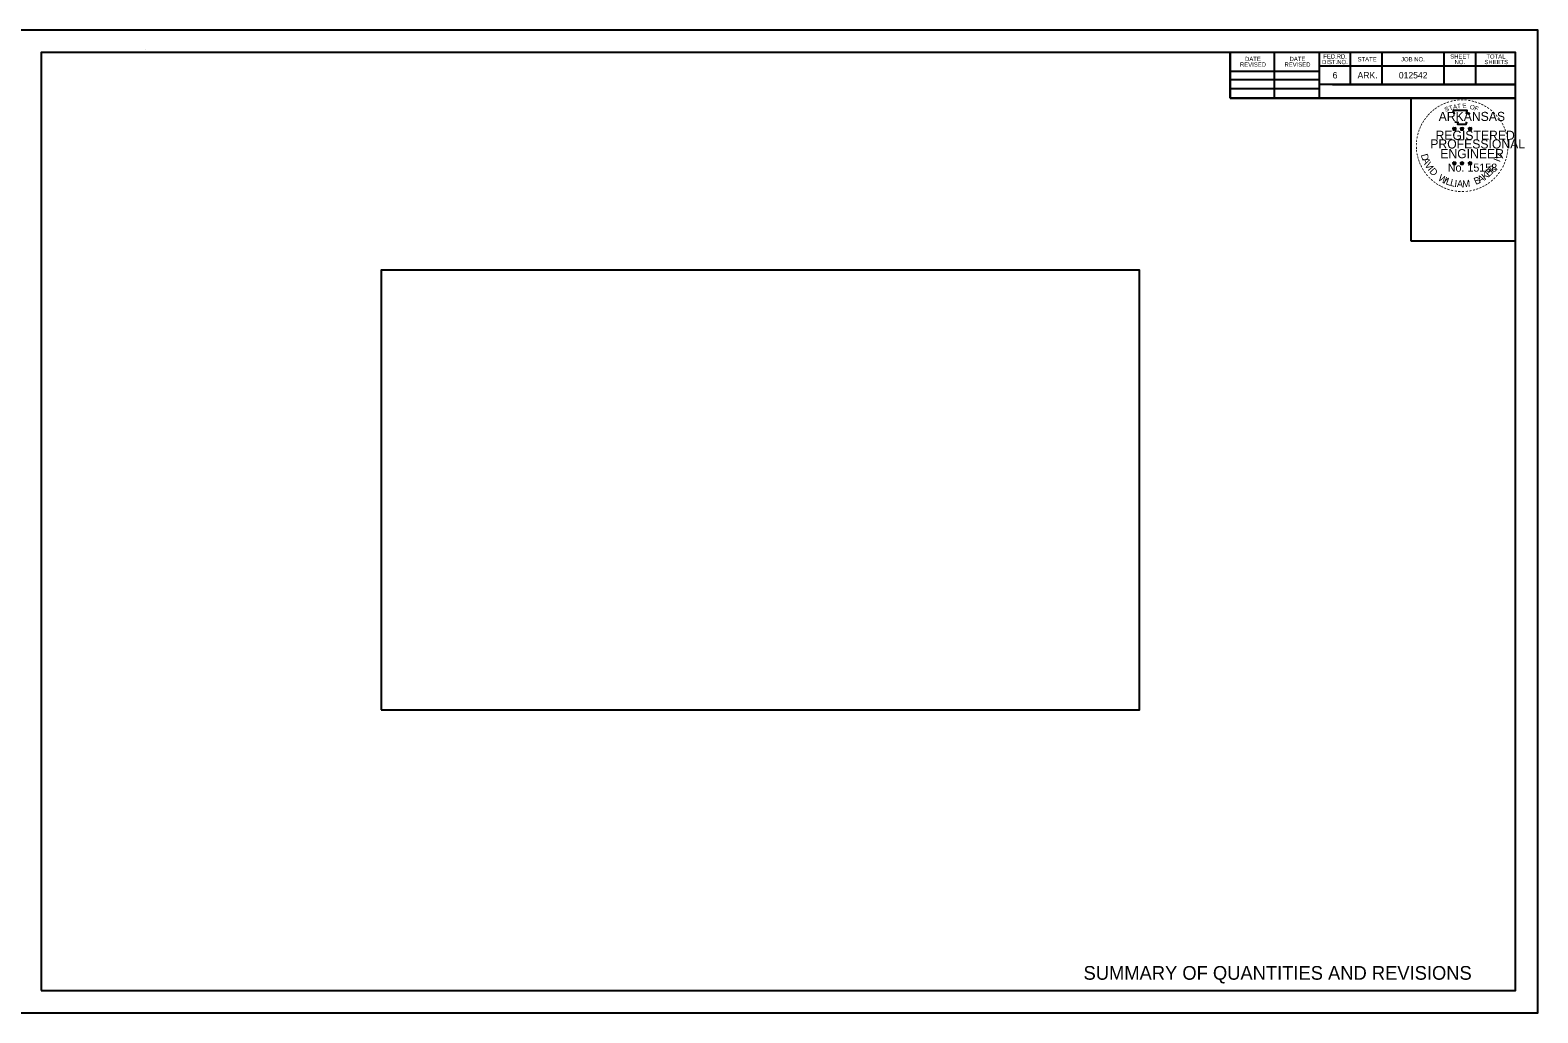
# Model space of a CAD drawing. Extents: x 2260866 to 2265966, y -3124874 to -3123774.
# Drawn here: x 2264278 to 2265966, y -3124874 to -3123774 of the extents above; entities that cross this region are included whole.
import ezdxf

# ---------------------------------------------------------------- set-up
doc = ezdxf.new("R2010")
doc.units = 0
for name, color, linetype in [('Default', 7, 'Continuous'), ('R_Border PE', 7, 'Continuous'), ('SHET_Annotations', 7, 'Continuous'), ('SHET_Border-Lines', 7, 'Continuous'), ('SHET_Border-Text', 7, 'Continuous'), ('SHET_Stamp-PE-Chief-Eng', 7, 'Continuous'), ('SHET_Stamp-Prelim', 7, 'Continuous'), ('SHET_Stamp-Seal', 7, 'Continuous')]:
    doc.layers.add(name, color=color, linetype=linetype)

msp = doc.modelspace()

# ---------------------------------------------------------------- linework, layer by layer
at = {"layer": 'Default'}
for points in [[(2264265.7, -3123773.5), (2264265.7, -3124873.5), (2265965.7, -3124873.5), (2265965.7, -3123773.5)], [(2264671.2, -3124534.4), (2265520, -3124534.4), (2265520, -3124042.2), (2264671.2, -3124042.2)]]:
    msp.add_lwpolyline(points, close=True, dxfattribs=at)
at = {"layer": 'R_Border PE'}
for p, q in [((2265872.3, -3123882), (2265872.1, -3123883.3)), ((2265872.3, -3123883.8), (2265872.3, -3123882)), ((2265872.3, -3123882), (2265872.5, -3123883.3)), ((2265880.8, -3123882), (2265880.6, -3123883.3)), ((2265880.8, -3123883.8), (2265880.8, -3123882)), ((2265880.8, -3123882), (2265881, -3123883.3)), ((2265889.8, -3123882), (2265889.6, -3123883.3)), ((2265889.8, -3123883.9), (2265889.8, -3123882)), ((2265889.8, -3123882), (2265890, -3123883.3)), ((2265870.5, -3123883.3), (2265872.3, -3123883.8)), ((2265870.5, -3123883.3), (2265871.8, -3123883.5)), ((2265870.5, -3123883.3), (2265871.7, -3123883.9)), ((2265871.2, -3123885.4), (2265872.3, -3123883.8)), ((2265871.2, -3123885.4), (2265871.8, -3123884.1)), ((2265871.2, -3123885.4), (2265872.3, -3123884.3)), ((2265874, -3123883.3), (2265872.3, -3123883.8)), ((2265873.4, -3123885.4), (2265872.3, -3123883.8)), ((2265873.4, -3123885.4), (2265872.3, -3123884.3)), ((2265874, -3123883.3), (2265872.6, -3123883.5)), ((2265873.4, -3123885.4), (2265872.7, -3123883.9)), ((2265874, -3123883.3), (2265873, -3123883.8)), ((2265879, -3123883.3), (2265880.8, -3123883.8)), ((2265879, -3123883.3), (2265880.3, -3123883.5)), ((2265879, -3123883.3), (2265880.2, -3123883.9)), ((2265879.7, -3123885.4), (2265880.8, -3123883.8)), ((2265879.7, -3123885.4), (2265880.3, -3123884.1)), ((2265879.7, -3123885.4), (2265880.8, -3123884.3)), ((2265882.6, -3123883.3), (2265880.8, -3123883.8)), ((2265881.9, -3123885.4), (2265880.8, -3123883.8)), ((2265881.9, -3123885.4), (2265880.8, -3123884.3)), ((2265882.6, -3123883.3), (2265881.1, -3123883.5)), ((2265881.9, -3123885.4), (2265881.2, -3123883.9)), ((2265882.6, -3123883.3), (2265881.5, -3123883.8)), ((2265888, -3123883.3), (2265889.8, -3123883.9)), ((2265888, -3123883.3), (2265889.3, -3123883.6)), ((2265888, -3123883.3), (2265889.2, -3123884)), ((2265888.7, -3123885.4), (2265889.8, -3123883.9)), ((2265888.7, -3123885.4), (2265889.3, -3123884.2)), ((2265888.7, -3123885.4), (2265889.8, -3123884.3)), ((2265891.6, -3123883.3), (2265889.8, -3123883.9)), ((2265890.9, -3123885.4), (2265889.8, -3123883.9)), ((2265890.9, -3123885.4), (2265889.8, -3123884.3)), ((2265891.6, -3123883.3), (2265890.1, -3123883.6)), ((2265890.9, -3123885.4), (2265890.2, -3123883.9)), ((2265891.6, -3123883.3), (2265890.5, -3123883.9)), ((2265870.5, -3123921.9), (2265872.3, -3123922.5)), ((2265870.5, -3123921.9), (2265871.8, -3123922.1)), ((2265870.5, -3123921.9), (2265871.7, -3123922.5)), ((2265871.2, -3123924), (2265872.3, -3123922.5)), ((2265871.2, -3123924), (2265871.8, -3123922.7)), ((2265871.2, -3123924), (2265872.2, -3123922.9)), ((2265872.3, -3123920.6), (2265872, -3123921.9)), ((2265873.3, -3123924), (2265872.2, -3123922.9)), ((2265872.3, -3123922.5), (2265872.3, -3123920.6)), ((2265872.3, -3123920.6), (2265872.5, -3123921.9)), ((2265874, -3123921.9), (2265872.3, -3123922.5)), ((2265873.3, -3123924), (2265872.3, -3123922.5)), ((2265874, -3123921.9), (2265872.6, -3123922.2)), ((2265873.3, -3123924), (2265872.6, -3123922.5)), ((2265874, -3123921.9), (2265873, -3123922.4)), ((2265879, -3123921.9), (2265880.8, -3123922.5)), ((2265879, -3123921.9), (2265880.3, -3123922.1)), ((2265879, -3123921.9), (2265880.2, -3123922.5)), ((2265879.7, -3123924), (2265880.8, -3123922.5)), ((2265879.7, -3123924), (2265880.3, -3123922.7)), ((2265879.7, -3123924), (2265880.8, -3123922.9)), ((2265880.8, -3123920.6), (2265880.6, -3123921.9)), ((2265880.8, -3123922.5), (2265880.8, -3123920.6)), ((2265880.8, -3123920.6), (2265881, -3123921.9)), ((2265882.5, -3123921.9), (2265880.8, -3123922.5)), ((2265881.9, -3123924), (2265880.8, -3123922.5)), ((2265881.9, -3123924), (2265880.8, -3123922.9)), ((2265882.5, -3123921.9), (2265881.1, -3123922.2)), ((2265881.9, -3123924), (2265881.2, -3123922.5)), ((2265882.5, -3123921.9), (2265881.5, -3123922.4)), ((2265888, -3123922), (2265889.8, -3123922.5)), ((2265888, -3123922), (2265889.3, -3123922.2)), ((2265888, -3123922), (2265889.2, -3123922.6)), ((2265888.7, -3123924), (2265889.8, -3123922.5)), ((2265888.7, -3123924), (2265889.3, -3123922.8)), ((2265888.7, -3123924), (2265889.8, -3123922.9)), ((2265889.8, -3123920.7), (2265889.6, -3123921.9)), ((2265889.8, -3123922.5), (2265889.8, -3123920.7)), ((2265889.8, -3123920.7), (2265890, -3123921.9)), ((2265891.5, -3123922), (2265889.8, -3123922.5)), ((2265890.9, -3123924), (2265889.8, -3123922.5)), ((2265890.9, -3123924), (2265889.8, -3123922.9)), ((2265891.5, -3123922), (2265890.1, -3123922.2)), ((2265890.9, -3123924), (2265890.2, -3123922.5)), ((2265891.5, -3123922), (2265890.5, -3123922.5))]:
    msp.add_line(p, q, dxfattribs=at)
for points in [[(2265870.7, -3123863.5), (2265872.1, -3123867.7)], [(2265888.6, -3123868.2), (2265889.3, -3123866.8), (2265885.8, -3123866.9), (2265886.6, -3123863.5), (2265870.7, -3123863.5)], [(2265873.2, -3123875.9), (2265873.2, -3123876.3), (2265876.1, -3123876.4), (2265875.8, -3123878.8), (2265885.3, -3123878.8), (2265886.4, -3123876.1)], [(2265880.8, -3123882), (2265881.9, -3123885.4), (2265879, -3123883.3), (2265882.6, -3123883.3), (2265879.7, -3123885.4), (2265880.8, -3123882)], [(2265889.8, -3123882), (2265890.9, -3123885.4), (2265888, -3123883.3), (2265891.6, -3123883.3), (2265888.7, -3123885.4), (2265889.8, -3123882)], [(2265872.3, -3123920.6), (2265873.3, -3123924), (2265870.5, -3123921.9), (2265874, -3123921.9), (2265871.2, -3123924), (2265872.3, -3123920.6)], [(2265880.8, -3123920.6), (2265881.9, -3123924), (2265879, -3123921.9), (2265882.5, -3123921.9), (2265879.7, -3123924), (2265880.8, -3123920.6)], [(2265889.8, -3123920.7), (2265890.9, -3123924), (2265888, -3123922), (2265891.5, -3123922), (2265888.7, -3123924), (2265889.8, -3123920.7)]]:
    msp.add_lwpolyline(points, dxfattribs=at)
for centre, radius in [((2265872.3, -3123883.9), 0.878), ((2265872.3, -3123883.9), 0.737), ((2265880.8, -3123883.9), 0.878), ((2265880.8, -3123883.9), 0.737), ((2265889.8, -3123883.9), 0.878), ((2265872.3, -3123883.9), 0.59), ((2265872.3, -3123883.9), 0.505), ((2265872.3, -3123883.9), 0.381), ((2265872.3, -3123883.9), 0.253), ((2265872.3, -3123883.9), 0.151), ((2265880.8, -3123883.9), 0.59), ((2265880.8, -3123883.9), 0.505), ((2265880.8, -3123883.9), 0.381), ((2265880.8, -3123883.9), 0.253), ((2265880.8, -3123883.9), 0.151), ((2265889.8, -3123883.9), 0.737), ((2265889.8, -3123883.9), 0.59), ((2265889.8, -3123883.9), 0.505), ((2265889.8, -3123883.9), 0.381), ((2265889.8, -3123883.9), 0.253), ((2265889.8, -3123883.9), 0.151), ((2265872.2, -3123922.5), 0.878), ((2265872.2, -3123922.5), 0.737), ((2265872.2, -3123922.5), 0.59), ((2265872.2, -3123922.5), 0.505), ((2265872.2, -3123922.5), 0.381), ((2265872.2, -3123922.5), 0.253), ((2265872.2, -3123922.5), 0.151), ((2265880.8, -3123922.5), 0.878), ((2265880.8, -3123922.5), 0.737), ((2265880.8, -3123922.5), 0.59), ((2265880.8, -3123922.5), 0.505), ((2265880.8, -3123922.5), 0.381), ((2265880.8, -3123922.5), 0.253), ((2265880.8, -3123922.5), 0.151), ((2265889.8, -3123922.5), 0.878), ((2265889.8, -3123922.5), 0.737), ((2265889.8, -3123922.5), 0.59), ((2265889.8, -3123922.5), 0.505), ((2265889.8, -3123922.5), 0.381), ((2265889.8, -3123922.5), 0.253), ((2265889.8, -3123922.5), 0.151)]:
    msp.add_circle(centre, radius, dxfattribs=at)
at = {"layer": 'SHET_Border-Lines'}
for p, q in [((2264406.8, -3123795), (2264406.8, -3123795)), ((2264406.8, -3123795), (2264406.8, -3123795)), ((2265621.2, -3123849.5), (2265621.2, -3123798.5)), ((2265671.1, -3123849.5), (2265671.1, -3123798.5)), ((2265720.9, -3123798.5), (2265720.9, -3123849.5)), ((2265755.8, -3123798.5), (2265755.8, -3123834.3)), ((2265791.2, -3123798.5), (2265791.2, -3123834.3)), ((2265860.4, -3123798.5), (2265860.4, -3123834.3)), ((2265895.8, -3123798.5), (2265895.8, -3123834.3)), ((2265940.7, -3123813.7), (2265720.9, -3123813.7)), ((2265940.7, -3123813.6), (2265940.7, -3123813.6)), ((2265621.2, -3123819.3), (2265720.9, -3123819.3)), ((2265621.2, -3123828.9), (2265720.9, -3123828.9)), ((2265621.2, -3123838.9), (2265720.9, -3123838.9)), ((2265940.7, -3123834.3), (2265720.9, -3123834.3)), ((2265736, -3123834.3), (2265940.7, -3123834.3)), ((2265940.7, -3123849.5), (2265621.2, -3123849.5))]:
    msp.add_line(p, q, dxfattribs=at)
for points in [[(2264265.7, -3124873.5), (2265965.7, -3124873.5), (2265965.7, -3123773.5), (2264265.7, -3123773.5)], [(2264290.7, -3124848.5), (2265940.7, -3124848.5), (2265940.7, -3123798.5), (2264290.7, -3123798.5)], [(2265621.2, -3123849.5), (2265940.7, -3123849.5), (2265940.7, -3123798.5), (2265621.2, -3123798.5)]]:
    msp.add_lwpolyline(points, close=True, dxfattribs=at)
at = {"layer": 'SHET_Stamp-PE-Chief-Eng'}
msp.add_lwpolyline([(2265872.3, -3123882), (2265873.4, -3123885.4), (2265870.5, -3123883.3), (2265874, -3123883.3), (2265871.2, -3123885.4), (2265872.3, -3123882)], dxfattribs=at)
at = {"layer": 'SHET_Stamp-Prelim'}
msp.add_lwpolyline([(2265830.7, -3123849.5), (2265830.9, -3123849.5), (2265830.9, -3123849.5), (2265830.7, -3123849.5)], close=True, dxfattribs=at)
at = {"layer": 'SHET_Stamp-Seal'}
msp.add_lwpolyline([(2265823.7, -3124009.2), (2265940.7, -3124009.2), (2265940.7, -3123849.5), (2265823.7, -3123849.5)], close=True, dxfattribs=at)

# ---------------------------------------------------------------- texts
at = {"layer": 'Default'}
msp.add_text('SUMMARY OF QUANTITIES AND REVISIONS', height=15.349, dxfattribs=at).set_placement((2265457.2, -3124836.5))
at = {"layer": 'R_Border PE'}
for s, height, rotation, p in [('-', 8.16, 42.9622, (2265847.2, -3123868.7)), ('-', 8.16, 38.9507, (2265849.4, -3123866.6)), ('-', 8.16, 36.2317, (2265851.9, -3123864.6)), ('-', 8.16, 34.0636, (2265854.8, -3123862.6)), ('-', 8.16, 28.7918, (2265857.9, -3123860.7)), ('-', 8.16, 24.3072, (2265861.1, -3123859.1)), ('S', 5.1, 21.594, (2265862.3, -3123865.1)), ('-', 8.16, 19.1761, (2265864.3, -3123857.8)), ('T', 5.1, 16.4036, (2265867, -3123863.5)), ('-', 8.16, 13.6302, (2265868.1, -3123856.5)), ('A', 5.1, 11.2132, (2265871.2, -3123862.2)), ('-', 8.16, 10.2193, (2265871.6, -3123855.7)), ('T', 5.1, 6.0228, (2265875.5, -3123861.3)), ('-', 8.16, 5.8968, (2265875.3, -3123855.1)), ('-', 8.16, 0.1862, (2265879.3, -3123854.8)), ('E', 5.1, 0.8323, (2265881.2, -3123860.8)), ('-', 8.16, 357.743, (2265882.9, -3123854.8)), ('-', 8.16, 352.1617, (2265886.7, -3123855.1)), ('O', 5.1, 350.4515, (2265889.3, -3123861.8)), ('-', 8.16, 347.2049, (2265890.4, -3123855.7)), ('F', 5.1, 340.0707, (2265894.2, -3123863)), ('-', 8.16, 342.3362, (2265893.6, -3123856.5)), ('-', 8.16, 337.8551, (2265897.4, -3123857.6)), ('-', 8.16, 334.1211, (2265900.6, -3123859)), ('-', 8.16, 329.6409, (2265903.6, -3123860.5)), ('-', 8.16, 325.8627, (2265906.8, -3123862.3)), ('-', 8.16, 320.5297, (2265910, -3123864.5)), ('-', 8.16, 315.5786, (2265913, -3123867)), ('-', 8.16, 67.7743, (2265836.2, -3123885.4)), ('-', 8.16, 62.8713, (2265837.5, -3123882.3)), ('-', 8.16, 58.0706, (2265839.1, -3123879.2)), ('-', 8.16, 54.2325, (2265840.8, -3123876.5)), ('-', 8.16, 50.6142, (2265842.9, -3123873.6)), ('-', 8.16, 48.4231, (2265844.9, -3123871.1)), ('-', 8.16, 309.8797, (2265915.9, -3123869.8)), ('-', 8.16, 306.6522, (2265918.6, -3123872.8)), ('-', 7.14, 303.6753, (2265921.1, -3123875.7)), ('-', 8.16, 299.6684, (2265922.7, -3123878.8)), ('-', 8.16, 294.6628, (2265924.3, -3123881.9)), ('-', 8.16, 89.0622, (2265832.9, -3123903)), ('-', 8.16, 85.1863, (2265833, -3123899.5)), ('-', 8.16, 81.2013, (2265833.4, -3123895.9)), ('-', 8.16, 75.461, (2265834.1, -3123892.3)), ('-', 8.16, 72.3945, (2265835.1, -3123888.7)), ('-', 8.16, 290.5728, (2265925.7, -3123884.9)), ('-', 8.16, 285.1233, (2265926.8, -3123887.8)), ('-', 8.16, 280.5493, (2265927.9, -3123891.6)), ('-', 8.16, 276.5962, (2265928.7, -3123895.6)), ('-', 8.16, 274.3301, (2265929, -3123899.2)), ('-', 8.16, 94.1959, (2265833.1, -3123906.7)), ('-', 8.16, 98.9479, (2265833.4, -3123910.1)), ('-', 8.16, 101.7149, (2265834.1, -3123913.9)), ('-', 8.16, 105.4578, (2265835, -3123916.9)), ('D', 7.85, 286.2848, (2265834.6, -3123913.2)), ('V', 7.85, 72.6573, (2265924.3, -3123919.1)), ('-', 8.16, 255.7626, (2265928.2, -3123912.6)), ('-', 8.16, 260.9953, (2265928.7, -3123909.2)), ('-', 8.16, 263.5172, (2265929.1, -3123905.9)), ('-', 8.16, 269.9407, (2265929.2, -3123902.5)), ('-', 8.16, 109.0874, (2265836.1, -3123920.1)), ('-', 8.16, 114.0643, (2265837.3, -3123923.2)), ('-', 8.16, 115.7289, (2265838.9, -3123926.3)), ('-', 8.16, 120.4471, (2265840.7, -3123929.3)), ('A', 7.85, 292.7835, (2265836.1, -3123918.3)), ('-', 8.16, 125.8934, (2265842.8, -3123932.2)), ('V', 7.85, 300.7936, (2265838.7, -3123924.3)), ('I', 7.85, 308.3502, (2265841.9, -3123929.6)), ('D', 7.85, 311.9774, (2265843.7, -3123932)), ('K', 7.85, 36.9143, (2265906.4, -3123941.7)), ('E', 7.85, 44.0175, (2265911, -3123938.1)), ('R', 7.85, 50.3651, (2265914.8, -3123934.5)), ('I', 7.85, 69.0301, (2265923.2, -3123921.8)), (',', 7.85, 57.4684, (2265918.4, -3123930)), ('-', 8.16, 233.8452, (2265920.7, -3123930.1)), ('-', 8.16, 239.0712, (2265922.7, -3123926.8)), ('-', 8.16, 244.6197, (2265924.8, -3123923)), ('-', 8.16, 247.8887, (2265926.1, -3123919.7)), ('-', 8.16, 252.8681, (2265927.2, -3123916.3)), ('-', 8.16, 130.7181, (2265845.1, -3123935)), ('-', 8.16, 134.2238, (2265847.8, -3123937.8)), ('-', 8.16, 138.9338, (2265850.5, -3123940.1)), ('-', 8.16, 144.6463, (2265853.3, -3123942.2)), ('-', 8.16, 148.0898, (2265856.1, -3123944.1)), ('-', 8.16, 151.5704, (2265859.1, -3123945.7)), ('W', 7.85, 328.0731, (2265853.3, -3123941)), ('-', 8.16, 154.6002, (2265861.8, -3123947)), ('I', 7.85, 336.6877, (2265859.3, -3123944.6)), ('-', 8.16, 158.5612, (2265864.9, -3123948.3)), ('L', 7.85, 340.3149, (2265862, -3123945.8)), ('L', 7.85, 346.6625, (2265866.9, -3123947.6)), ('I', 7.85, 353.0101, (2265872, -3123948.8)), ('A', 7.85, 356.6373, (2265874.9, -3123949.2)), ('M', 7.85, 4.6473, (2265881.5, -3123949.5)), ('B', 7.85, 22.8589, (2265896.1, -3123946.8)), ('-', 8.16, 199.4643, (2265898.6, -3123947.7)), ('A', 7.85, 28.9042, (2265900.7, -3123944.9)), ('-', 8.16, 204.2516, (2265901.8, -3123946.3)), ('-', 8.16, 207.3568, (2265905, -3123944.6)), ('-', 8.16, 212.2491, (2265907.9, -3123942.9)), ('-', 8.16, 215.7363, (2265910.6, -3123940.9)), ('-', 8.16, 221.0851, (2265913.4, -3123938.5)), ('-', 8.16, 225.7653, (2265916.1, -3123935.9)), ('-', 8.16, 231.2538, (2265918.5, -3123933)), ('-', 8.16, 162.7983, (2265868.4, -3123949.4)), ('-', 8.16, 167.5555, (2265872.1, -3123950.2)), ('-', 8.16, 173.1155, (2265876, -3123950.8)), ('-', 8.16, 176.5183, (2265879.8, -3123951.1)), ('-', 8.16, 181.5918, (2265883.6, -3123951)), ('-', 8.16, 185.8167, (2265887.8, -3123950.6)), ('-', 8.16, 191.2858, (2265891.5, -3123949.9)), ('-', 8.16, 195.4743, (2265895.2, -3123948.9))]:
    msp.add_text(s, height=height, rotation=rotation, dxfattribs=at).set_placement(p)
for s, height, p in [('ARKANSAS', 10.2, (2265854.7, -3123875.2)), ('PROFESSIONAL', 10.2, (2265845.3, -3123906)), ('REGISTERED', 10.2, (2265851.2, -3123896.3)), ('ENGINEER', 10.2, (2265856.5, -3123916.9)), ('No. 15158', 8.96, (2265864.9, -3123931.9)), ('AAMU', 0.000102, (2265880.4, -3123949.5))]:
    msp.add_text(s, height=height, dxfattribs=at).set_placement(p)
at = {"layer": 'SHET_Annotations'}
for s, p in [('6', (2265736, -3123827.6)), ('ARK.', (2265763.9, -3123827.6)), ('012542', (2265810.1, -3123827.6))]:
    msp.add_text(s, height=7.2, dxfattribs=at).set_placement(p)
at = {"layer": 'SHET_Border-Text'}
for s, p in [('REVISED', (2265632.3, -3123814.4)), ('DATE', (2265638, -3123808.2)), ('REVISED', (2265682.1, -3123814.4)), ('DATE', (2265687.8, -3123808.2)), ('DIST.NO.', (2265724.2, -3123811.6)), ('FED.RD.', (2265725.5, -3123805.4)), ('STATE', (2265763.9, -3123808.5)), ('JOB NO.', (2265812.6, -3123808.5)), ('SHEET', (2265867.6, -3123805.4)), ('NO.', (2265872.5, -3123811.6)), ('SHEETS', (2265905.9, -3123811.6)), ('TOTAL', (2265908.1, -3123805.4))]:
    msp.add_text(s, height=4.8, dxfattribs=at).set_placement(p)
at = {"layer": 'SHET_Stamp-Prelim'}
for s, height in [('PRELIMINARY', 0.013), ('SUBJECT TO REVISION', 0.009)]:
    msp.add_text(s, height=height, dxfattribs=at).set_placement((2265830.7, -3123849.5))

doc.saveas('drawing.dxf')
